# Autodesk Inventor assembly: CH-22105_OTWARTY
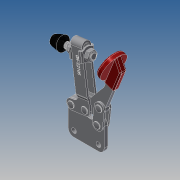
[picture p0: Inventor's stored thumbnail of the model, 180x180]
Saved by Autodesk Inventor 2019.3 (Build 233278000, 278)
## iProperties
Company: Microsoft
Created: 2017-06
Part Number: CH-22105_OTWARTY
Material: Ogólny
Description: STEP AP203
Document SubType Name: Assembly
Designer: CADENGINEERING4
Sending System: SolidWorks 2015
Preprocessor: SwSTEP 2.0
Title: CH-22105.STEP
Author: Windows
Revision Number: ÈÎºÎ
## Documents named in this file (9)
- E:\STRONA\Horizontal toggle clamp\CH-22105\CH-22105_OTWARTY.iam
- E:\STRONA\Horizontal toggle clamp\CH-22105\22105-01.ipt
- E:\STRONA\Horizontal toggle clamp\CH-22105\14134.ipt
- E:\STRONA\Horizontal toggle clamp\CH-22105\14134-02.ipt
- E:\STRONA\Horizontal toggle clamp\CH-22105\22105-02.ipt
- E:\STRONA\Horizontal toggle clamp\CH-22105\22105-03.ipt
- E:\STRONA\Horizontal toggle clamp\CH-22105\22105-04.ipt
- E:\STRONA\Horizontal toggle clamp\CH-22105\FW140.ipt
- E:\STRONA\Horizontal toggle clamp\CH-22105\22105-05.ipt
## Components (14 placed, 14 different names)
1. 22105-01_1 — Zestawiające:10, Zestawiające:11, Zestawiające:12, Zestawiające:13, Zestawiające:21, Zestawiające:22, Przejściowe:1
2. 14134_2 — Równoległe:1, Zestawiające:1, Zestawiające:2, Zestawiające:5, Zestawiające:7, Zestawiające:9
3. 14134-02_3 — Zestawiające:2, Zestawiające:3
4. 22105-02_4 — Równoległe:2, Zestawiające:4, Zestawiające:6, Zestawiające:9, Zestawiające:21, Zestawiające:22, Zestawiające:23, Zestawiające:24, Zestawiające:25, Zestawiające:26
5. 22105-03_5 — Zestawiające:17, Zestawiające:18, Zestawiające:27, Przejściowe:1
6. 22105-04_6 — Zestawiające:10, Zestawiające:13, Zestawiające:14, Zestawiające:15, Zestawiające:16, Zestawiające:17, Zestawiające:18, Zestawiające:19, Zestawiające:20
7. FW140_7 — Równoległe:3, Zestawiające:5, Zestawiające:6, Zestawiające:8
8. 22105-04_8 — Zestawiające:11, Zestawiające:12, Zestawiające:14
9. FW140_9 — Równoległe:2, Równoległe:3, Zestawiające:1, Zestawiające:3, Zestawiające:4
10. 14134-02_10 — Równoległe:1, Zestawiające:7, Zestawiające:8
11. 22105-05_11 — Zestawiające:19, Zestawiające:20
12. 22105-05_12 — Zestawiające:25, Zestawiające:26, Zestawiające:27
13. 22105-05_13 — Zestawiające:15, Zestawiające:16
14. 22105-05_14 — Zestawiające:23, Zestawiające:24
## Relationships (31: Mate 27, Flush 3, Transitional 1)
- Równoległe:1 [Flush]: 14134_2 ↔ 14134-02_10
- Równoległe:2 [Flush]: 22105-02_4 ↔ FW140_9
- Równoległe:3 [Flush]: FW140_7 ↔ FW140_9
- Zestawiające:1 [Mate]: 14134_2 ↔ FW140_9
- Zestawiające:2 [Mate]: 14134_2 ↔ 14134-02_3
- Zestawiające:3 [Mate]: 14134-02_3 ↔ FW140_9
- Zestawiające:4 [Mate]: 22105-02_4 ↔ FW140_9
- Zestawiające:5 [Mate]: 14134_2 ↔ FW140_7
- Zestawiające:6 [Mate]: 22105-02_4 ↔ FW140_7
- Zestawiające:7 [Mate]: 14134_2 ↔ 14134-02_10
- Zestawiające:8 [Mate]: FW140_7 ↔ 14134-02_10
- Zestawiające:9 [Mate]: 14134_2 ↔ 22105-02_4
- Zestawiające:10 [Mate]: 22105-01_1 ↔ 22105-04_6
- Zestawiające:11 [Mate]: 22105-01_1 ↔ 22105-04_8
- Zestawiające:12 [Mate]: 22105-01_1 ↔ 22105-04_8
- Zestawiające:13 [Mate]: 22105-01_1 ↔ 22105-04_6
- Zestawiające:14 [Mate]: 22105-04_6 ↔ 22105-04_8
- Zestawiające:15 [Mate]: 22105-04_6 ↔ 22105-05_13
- Zestawiające:16 [Mate]: 22105-04_6 ↔ 22105-05_13
- Zestawiające:17 [Mate]: 22105-03_5 ↔ 22105-04_6
- Zestawiające:18 [Mate]: 22105-03_5 ↔ 22105-04_6
- Zestawiające:19 [Mate]: 22105-04_6 ↔ 22105-05_11
- Zestawiające:20 [Mate]: 22105-04_6 ↔ 22105-05_11
- Zestawiające:21 [Mate]: 22105-01_1 ↔ 22105-02_4
- Zestawiające:22 [Mate]: 22105-01_1 ↔ 22105-02_4
- Zestawiające:23 [Mate]: 22105-02_4 ↔ 22105-05_14
- Zestawiające:24 [Mate]: 22105-02_4 ↔ 22105-05_14
- Zestawiające:25 [Mate]: 22105-02_4 ↔ 22105-05_12
- Zestawiające:26 [Mate]: 22105-02_4 ↔ 22105-05_12
- Zestawiające:27 [Mate]: 22105-03_5 ↔ 22105-05_12
- Przejściowe:1 [Transitional]: 22105-01_1 ↔ 22105-03_5
